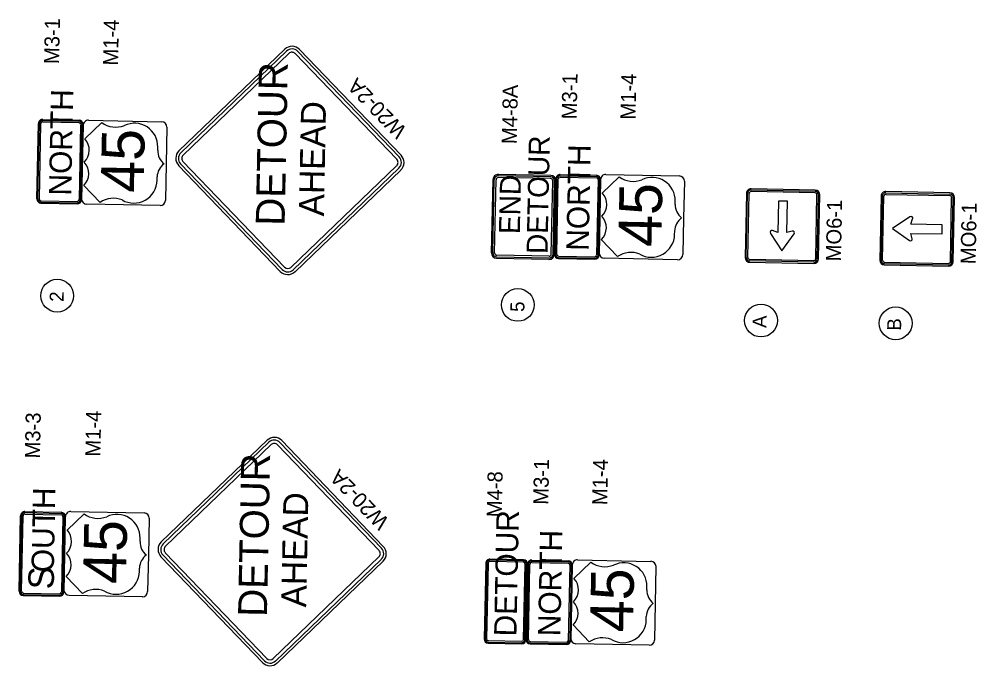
# Model space of a CAD drawing. Extents: x 345549 to 379569, y 127949 to 230467.
# Drawn here: x 352156 to 362441, y 217160 to 224101 of the extents above; entities that cross this region are included whole.
import ezdxf

# ---------------------------------------------------------------- set-up
doc = ezdxf.new("R2010")
doc.units = 0
doc.layers.add('CA-TEXT', color=7, linetype='Continuous')
doc.layers.add('P_SGN_Cell', color=7, linetype='Continuous')

msp = doc.modelspace()

# ---------------------------------------------------------------- linework, layer by layer
at = {"layer": 'CA-TEXT'}
for centre in [(352565, 221133), (357511, 221034), (360123, 220866), (361569, 220837)]:
    msp.add_circle(centre, 176, dxfattribs=at)
at = {"layer": 'P_SGN_Cell'}
for p, q in [((352346, 222171), (352363, 222982)), ((352358, 222172), (352374, 222981)), ((352373, 222171), (352389, 222981)), ((352408, 223014), (352798, 223007)), ((352408, 222999), (352798, 222992)), ((352409, 223026), (352799, 223018)), ((352816, 222972), (352800, 222163)), ((352831, 222972), (352815, 222162)), ((352843, 222972), (352826, 222162)), ((353043, 222992), (352860, 222817)), ((352900, 223016), (353687, 223000)), ((352827, 222173), (352842, 222961)), ((353742, 222943), (353734, 222549)), ((353742, 222943), (353742, 222943)), ((353644, 222694), (353645, 222729)), ((353734, 222549), (353726, 222155)), ((353637, 222372), (353638, 222408)), ((357229, 221592), (357245, 222379)), ((357243, 221591), (357259, 222379)), ((357262, 221591), (357278, 222378)), ((357864, 222390), (357301, 222401)), ((357864, 222423), (357302, 222434)), ((357864, 222409), (357302, 222420)), ((357871, 221579), (357887, 222366)), ((357890, 221578), (357905, 222366)), ((357904, 221578), (357920, 222389)), ((357904, 221578), (357920, 222366)), ((357915, 221579), (357931, 222388)), ((357930, 221578), (357946, 222388)), ((357965, 222406), (358355, 222399)), ((357966, 222433), (358356, 222425)), ((357966, 222421), (358356, 222414)), ((358374, 222379), (358357, 221570)), ((358389, 222379), (358372, 221569)), ((358384, 221592), (358400, 222379)), ((358400, 222379), (358384, 221569)), ((358600, 222410), (358418, 222235)), ((358457, 222434), (359245, 222419)), ((359300, 222361), (359292, 221967)), ((359300, 222361), (359300, 222361)), ((352850, 222317), (353025, 222134)), ((360705, 222266), (360016, 222280)), ((360705, 222253), (360016, 222267)), ((360705, 222237), (360016, 222251)), ((362152, 222237), (361463, 222251)), ((352391, 222152), (352781, 222144)), ((359201, 222112), (359202, 222148)), ((359966, 222232), (359952, 221543)), ((359965, 221543), (359979, 222232)), ((359982, 221542), (359996, 222231)), ((360309, 222149), (360302, 221813)), ((360407, 222147), (360309, 222149)), ((360401, 221811), (360407, 222147)), ((360710, 221528), (360724, 222217)), ((360726, 221527), (360740, 222216)), ((360740, 221527), (360753, 222216)), ((361412, 222203), (361399, 221514)), ((361412, 221514), (361426, 222202)), ((361428, 221513), (361442, 222202)), ((361462, 222238), (362151, 222224)), ((361462, 222221), (362151, 222208)), ((362156, 221499), (362170, 222187)), ((362173, 221498), (362187, 222187)), ((362186, 221498), (362200, 222187)), ((352390, 222126), (352780, 222118)), ((352391, 222137), (352781, 222129)), ((353669, 222100), (352882, 222116)), ((359292, 221967), (359284, 221574)), ((361722, 221980), (361534, 221856)), ((361733, 221901), (361751, 221957)), ((361534, 221856), (361717, 221724)), ((362069, 221894), (361733, 221901)), ((362067, 221796), (362069, 221894)), ((358408, 221735), (358583, 221553)), ((359195, 221791), (359196, 221826)), ((360223, 221802), (360348, 221614)), ((360302, 221813), (360246, 221832)), ((360348, 221614), (360479, 221797)), ((360458, 221827), (360401, 221811)), ((361747, 221745), (361731, 221802)), ((361731, 221802), (362067, 221796)), ((357847, 221537), (357284, 221548)), ((357846, 221523), (357284, 221534)), ((357847, 221556), (357285, 221567)), ((357948, 221559), (358338, 221551)), ((357948, 221544), (358338, 221536)), ((357948, 221533), (358338, 221525)), ((359227, 221519), (358439, 221535)), ((360000, 221493), (360689, 221479)), ((360690, 221508), (360001, 221522)), ((360690, 221492), (360001, 221506)), ((361447, 221493), (362136, 221479)), ((361447, 221477), (362136, 221463)), ((361447, 221464), (362136, 221450)), ((352156, 217961), (352172, 218772)), ((352167, 217962), (352184, 218772)), ((352182, 217961), (352199, 218771)), ((352218, 218816), (352608, 218808)), ((352218, 218805), (352608, 218797)), ((352218, 218790), (352608, 218782)), ((352626, 218763), (352610, 217953)), ((352641, 218762), (352625, 217952)), ((352652, 218762), (352636, 217952)), ((352637, 217975), (352652, 218762)), ((352853, 218793), (352670, 218618)), ((352710, 218817), (353497, 218801)), ((353552, 218744), (353544, 218350)), ((353552, 218744), (353552, 218744)), ((353454, 218495), (353455, 218531)), ((353544, 218350), (353536, 217957)), ((357599, 217442), (357616, 218252)), ((357611, 217442), (357627, 218252)), ((357626, 217442), (357642, 218252)), ((357661, 218285), (358051, 218277)), ((357661, 218270), (358051, 218262)), ((357662, 218296), (358051, 218288)), ((358069, 218243), (358053, 217433)), ((358084, 218243), (358068, 217433)), ((358096, 218243), (358079, 217433)), ((358080, 217455), (358096, 218243)), ((358296, 218274), (358114, 218099)), ((358153, 218298), (358940, 218282)), ((353447, 218174), (353448, 218209)), ((358995, 218225), (358987, 217831)), ((358995, 218225), (358995, 218225)), ((352660, 218118), (352835, 217936)), ((352201, 217942), (352591, 217934)), ((358897, 217976), (358898, 218011)), ((352200, 217927), (352590, 217919)), ((352200, 217916), (352590, 217908)), ((353479, 217902), (352692, 217917)), ((358987, 217831), (358980, 217437)), ((358891, 217654), (358891, 217690)), ((358104, 217599), (358279, 217417)), ((357644, 217423), (358034, 217415)), ((357643, 217396), (358033, 217389)), ((357644, 217408), (358034, 217400)), ((358922, 217382), (358135, 217398))]:
    msp.add_line(p, q, dxfattribs=at)
for points in [[(355008, 223780), (353872, 222689)], [(355028, 223759), (353892, 222668)], [(355052, 223733), (353916, 222642)], [(356211, 222597), (355120, 223732)], [(356236, 222622), (355146, 223757)], [(356257, 222641), (355166, 223777)], [(353915, 222574), (355006, 221438)], [(353869, 222529), (354960, 221394)], [(353889, 222549), (354980, 221413)], [(355074, 221437), (356210, 222528)], [(355099, 221411), (356235, 222502)], [(355119, 221390), (356255, 222481)], [(354818, 219581), (353682, 218490)], [(356067, 218443), (354976, 219578)], [(354838, 219560), (353702, 218469)], [(354862, 219535), (353726, 218444)], [(356021, 218398), (354930, 219534)], [(356046, 218423), (354956, 219558)], [(353699, 218351), (354790, 217215)], [(353725, 218375), (354816, 217240)], [(353679, 218331), (354770, 217195)], [(354884, 217238), (356020, 218329)], [(354909, 217212), (356045, 218303)], [(354929, 217192), (356065, 218283)], [(357166, 218261), (357149, 217451)], [(357177, 218261), (357161, 217451)], [(357192, 218260), (357176, 217451)], [(357571, 218287), (357211, 218294)], [(357571, 218272), (357211, 218279)], [(357572, 218298), (357212, 218305)], [(357573, 217443), (357589, 218252)], [(357588, 217442), (357604, 218252)], [(357599, 217442), (357616, 218252)], [(357194, 217431), (357554, 217424)], [(357194, 217416), (357554, 217409)], [(357194, 217405), (357553, 217398)]]:
    msp.add_lwpolyline(points, dxfattribs=at)
for centre, radius, start, end in [((355086, 223698), 112, 43.8468, 133.8468), ((355086, 223698), 83.9, 43.8468, 133.8468), ((355086, 223698), 48.2, 43.8468, 133.8468), ((352408, 222981), 45, 88.8462, 178.8462), ((352408, 222981), 33.7, 88.8462, 178.8462), ((352408, 222981), 18.7, 88.8462, 178.8462), ((352798, 222973), 33.7, 358.8462, 88.8462), ((352798, 222973), 18.7, 358.8462, 88.8462), ((352798, 222973), 45, 358.8462, 88.8462), ((352899, 222960), 56.2, 88.8462, 178.8462), ((353193, 223192), 250, 233.1143, 291.9873), ((353395, 222734), 250, 358.8462, 115.6928), ((353686, 222944), 56.2, 358.8462, 88.8462), ((352730, 222694), 179, 314.4191, 43.2734), ((353825, 222691), 181, 179.1885, 231.634), ((353950, 222607), 112, 133.8449, 223.8468), ((353950, 222607), 83.9, 133.8449, 223.8468), ((352725, 222444), 179, 314.4191, 43.2734), ((353950, 222607), 48.2, 133.8449, 223.8468), ((356177, 222563), 48.2, 313.854, 44.4977), ((356177, 222563), 83.9, 313.854, 44.4977), ((356177, 222563), 112, 313.854, 44.4977), ((353819, 222403), 181, 126.0584, 178.5039), ((353387, 222377), 250, 240.0981, 358.8463), ((357301, 222378), 56.2, 88.8468, 178.8468), ((357301, 222378), 42.2, 88.8468, 178.8468), ((357301, 222378), 23.4, 88.8468, 178.8468), ((357863, 222367), 56.2, 358.8468, 88.8468), ((357863, 222367), 42.2, 358.8468, 88.8468), ((357863, 222367), 23.4, 358.8468, 88.8468), ((357965, 222388), 45, 88.8462, 178.8462), ((357965, 222388), 33.7, 88.8462, 178.8462), ((357965, 222388), 18.7, 88.8462, 178.8462), ((358355, 222380), 18.7, 358.8462, 88.8462), ((358355, 222380), 45, 358.8462, 88.8462), ((358355, 222380), 33.7, 358.8462, 88.8462), ((358456, 222378), 56.2, 88.8462, 178.8462), ((358750, 222610), 250, 233.1143, 291.9873), ((358952, 222153), 250, 358.8462, 115.6928), ((359244, 222362), 56.2, 358.8462, 88.8462), ((360015, 222231), 49.2, 88.8462, 178.8462), ((360015, 222231), 36.1, 88.8462, 178.8462), ((360015, 222231), 19.7, 88.8462, 178.8462), ((360704, 222217), 49.2, 358.8462, 88.8462), ((360704, 222217), 36.1, 358.8462, 88.8462), ((361462, 222202), 49.2, 88.8462, 178.8462), ((352391, 222171), 45, 179.6119, 268.8462), ((352391, 222171), 33.7, 178.8462, 268.8462), ((352391, 222171), 18.7, 178.8462, 268.8462), ((352781, 222163), 45, 268.8462, 358.8462), ((352781, 222163), 18.7, 268.8462, 358.8462), ((352781, 222163), 33.7, 268.8462, 358.8462), ((352883, 222172), 56.2, 178.8462, 268.8462), ((353168, 221929), 250, 67.7159, 124.7982), ((353670, 222156), 56.2, 268.8462, 358.8462), ((358288, 222113), 179, 314.4191, 43.2734), ((360704, 222217), 19.7, 358.8462, 88.8462), ((361462, 222202), 49.2, 149.4497, 178.8462), ((361462, 222202), 36.1, 88.8462, 178.8462), ((361462, 222202), 19.7, 88.8462, 178.8462), ((362151, 222188), 36.1, 358.8462, 88.8462), ((362151, 222188), 19.7, 358.8462, 88.8462), ((362151, 222188), 49.2, 358.8462, 88.8462), ((359382, 222110), 181, 179.1885, 231.634), ((358283, 221863), 179, 314.4191, 43.2734), ((359376, 221822), 181, 126.0584, 178.5039), ((361733, 221963), 19.7, 342.0436, 123.3759), ((358945, 221796), 250, 240.0981, 358.8463), ((360240, 221813), 19.7, 72.0436, 213.3759), ((360463, 221808), 19.7, 324.3166, 105.6488), ((361728, 221740), 19.7, 234.3166, 15.6488), ((357285, 221591), 56.2, 178.8468, 268.8468), ((357285, 221591), 42.2, 178.8468, 268.8468), ((357285, 221591), 23.4, 178.8468, 268.8468), ((357285, 221591), 23.4, 178.8468, 187.6911), ((357847, 221579), 56.2, 268.8468, 358.8468), ((357847, 221579), 23.4, 268.8468, 358.8468), ((357847, 221579), 42.2, 268.8468, 358.8468), ((357949, 221578), 45, 179.6119, 268.8462), ((357949, 221578), 33.7, 178.8462, 268.8462), ((357949, 221578), 18.7, 178.8462, 268.8462), ((358339, 221570), 18.7, 268.8462, 358.8462), ((358339, 221570), 33.7, 268.8462, 358.8462), ((358339, 221570), 45, 268.8462, 358.8462), ((358440, 221591), 56.2, 178.8462, 268.8462), ((358726, 221348), 250, 67.7159, 124.7982), ((359228, 221575), 56.2, 268.8462, 358.8462), ((360001, 221542), 49.2, 178.8462, 268.8462), ((360001, 221542), 36.1, 178.8462, 268.8462), ((360001, 221542), 19.7, 178.8462, 268.8462), ((360690, 221528), 49.2, 268.8462, 358.8462), ((360690, 221528), 19.7, 268.8462, 358.8462), ((360690, 221528), 36.1, 268.8462, 358.8462), ((355041, 221472), 48.2, 223.8468, 313.8468), ((360001, 221542), 49.2, 239.4497, 268.8462), ((361448, 221513), 49.2, 178.8462, 268.8462), ((361448, 221513), 36.1, 178.8462, 268.8462), ((361448, 221513), 19.7, 178.8462, 268.8462), ((362137, 221499), 19.7, 268.8462, 358.8462), ((362137, 221499), 36.1, 268.8462, 358.8462), ((362137, 221499), 49.2, 268.8462, 358.8462), ((355041, 221472), 112, 223.8468, 313.8468), ((355041, 221472), 83.9, 223.8468, 313.8468), ((354896, 219500), 112, 43.8468, 133.8468), ((354896, 219500), 83.9, 43.8468, 133.8468), ((354896, 219500), 48.2, 43.8468, 133.8468), ((352217, 218771), 45, 88.8462, 178.8462), ((352217, 218771), 33.7, 88.8462, 178.8462), ((352217, 218771), 18.7, 88.8462, 178.8462), ((352607, 218763), 45, 358.8462, 88.8462), ((352607, 218763), 33.7, 358.8462, 88.8462), ((352607, 218763), 18.7, 358.8462, 88.8462), ((352709, 218761), 56.2, 88.8462, 178.8462), ((353003, 218993), 250, 233.1143, 291.9873), ((353205, 218536), 250, 358.8462, 115.6928), ((353496, 218745), 56.2, 358.8462, 88.8462), ((352540, 218496), 179, 314.4191, 43.2734), ((353635, 218492), 181, 179.1885, 231.634), ((353760, 218409), 112, 133.8449, 223.8468), ((353760, 218409), 83.9, 133.8449, 223.8468), ((353760, 218409), 48.2, 133.8449, 223.8468), ((355987, 218364), 112, 313.854, 44.4977), ((352535, 218246), 179, 314.4191, 43.2734), ((353629, 218205), 181, 126.0584, 178.5039), ((355987, 218364), 48.2, 313.854, 44.4977), ((355987, 218364), 83.9, 313.854, 44.4977), ((357211, 218260), 45, 88.8468, 178.8468), ((357211, 218260), 33.7, 88.8468, 178.8468), ((357211, 218260), 18.7, 88.8468, 178.8468), ((357571, 218253), 33.7, 358.8468, 88.8468), ((357571, 218253), 18.7, 358.8468, 88.8468), ((357571, 218253), 45, 358.8468, 88.8468), ((357661, 218251), 45, 88.8462, 178.8462), ((357661, 218251), 33.7, 88.8462, 178.8462), ((357661, 218251), 18.7, 88.8462, 178.8462), ((358051, 218243), 45, 358.8462, 88.8462), ((358051, 218243), 33.7, 358.8462, 88.8462), ((358051, 218243), 18.7, 358.8462, 88.8462), ((358152, 218242), 56.2, 88.8462, 178.8462), ((358446, 218474), 250, 233.1143, 291.9873), ((358648, 218016), 250, 358.8462, 115.6928), ((358939, 218226), 56.2, 358.8462, 88.8462), ((353197, 218179), 250, 240.0981, 358.8463), ((357984, 217976), 179, 314.4191, 43.2734), ((352201, 217961), 45, 179.6119, 268.8462), ((352201, 217961), 33.7, 178.8462, 268.8462), ((352201, 217961), 18.7, 178.8462, 268.8462), ((352591, 217953), 33.7, 268.8462, 358.8462), ((352591, 217953), 45, 268.8462, 358.8462), ((352591, 217953), 18.7, 268.8462, 358.8462), ((352693, 217974), 56.2, 178.8462, 268.8462), ((352978, 217731), 250, 67.7159, 124.7982), ((353480, 217958), 56.2, 268.8462, 358.8462), ((359078, 217973), 181, 179.1885, 231.634), ((357979, 217726), 179, 314.4191, 43.2734), ((359072, 217685), 181, 126.0584, 178.5039), ((358641, 217659), 250, 240.0981, 358.8463), ((357194, 217450), 45, 178.8468, 268.8468), ((357194, 217450), 33.7, 178.8468, 268.8468), ((357194, 217450), 18.7, 178.8468, 268.8468), ((357194, 217450), 18.7, 178.8468, 186.1883), ((357554, 217443), 45, 268.8468, 358.8468), ((357554, 217443), 18.7, 268.8468, 358.8468), ((357554, 217443), 33.7, 268.8468, 358.8468), ((357644, 217441), 45, 179.6119, 268.8462), ((357644, 217441), 33.7, 178.8462, 268.8462), ((357644, 217441), 18.7, 178.8462, 268.8462), ((358034, 217434), 45, 268.8462, 358.8462), ((358034, 217434), 33.7, 268.8462, 358.8462), ((358034, 217434), 18.7, 268.8462, 358.8462), ((358136, 217454), 56.2, 178.8462, 268.8462), ((358421, 217211), 250, 67.7159, 124.7982), ((358923, 217438), 56.2, 268.8462, 358.8462), ((354851, 217273), 83.9, 223.8468, 313.8468), ((354851, 217273), 48.2, 223.8468, 313.8468), ((354851, 217273), 112, 223.8468, 313.8468)]:
    msp.add_arc(centre, radius, start, end, dxfattribs=at)

# ---------------------------------------------------------------- texts
at = {"layer": 'CA-TEXT'}
for s, p in [('2', (352633, 221066)), ('5', (357581, 220958)), ('A', (360181, 220786)), ('B', (361627, 220757))]:
    msp.add_text(s, height=150, rotation=88.8468, dxfattribs=at).set_placement(p)
at = {"layer": 'P_SGN_Cell'}
for s, height, rotation, p in [('M3-1', 162, 88.8462, (352585, 223618)), ('M1-4', 162, 88.8462, (353218, 223602)), ('DETOUR', 310.7, 88.8468, (355007, 221882)), ('W20-2A', 162, 133.8468, (356328, 222917)), ('M3-1', 162, 88.8462, (358143, 223025)), ('M1-4', 162, 88.8462, (358775, 223021)), ('M4-8A', 162, 88.8468, (357500, 222759)), ('NORTH', 240, 88.8462, (352715, 222206)), ('AHEAD', 267.9, 88.8468, (355428, 221984)), ('45', 460, 88.8462, (353492, 222235)), ('DETOUR', 225, 88.8468, (357830, 221579)), ('NORTH', 240, 88.8462, (358272, 221613)), ('END', 225, 88.8468, (357533, 221793)), ('45', 460, 88.8462, (359050, 221654)), ('MO6-1', 162, 88.8462, (360981, 221500)), ('MO6-1', 162, 88.8462, (362427, 221470)), ('M1-4', 162, 88.8462, (353028, 219404)), ('M3-3', 162, 88.8462, (352379, 219385)), ('DETOUR', 310.7, 88.8468, (354817, 217684)), ('M3-1', 162, 88.8462, (357838, 218888)), ('M1-4', 162, 88.8462, (358471, 218884)), ('W20-2A', 162, 133.8468, (356138, 218718)), ('M4-8', 162, 88.8468, (357339, 218754)), ('OUTH', 240, 88.8462, (352528, 218163)), ('AHEAD', 267.9, 88.8468, (355238, 217786)), ('DETOUR', 240, 88.8468, (357496, 217474)), ('45', 460, 88.8462, (353302, 218037)), ('NORTH', 240, 88.8462, (357968, 217476)), ('S', 274, 88.8462, (352527, 217979)), ('45', 460, 88.8462, (358746, 217518))]:
    msp.add_text(s, height=height, rotation=rotation, dxfattribs=at).set_placement(p)

doc.saveas('drawing.dxf')
